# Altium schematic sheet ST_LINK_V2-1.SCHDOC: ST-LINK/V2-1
size A4; DocumentNumber: MB1167; Revision: B.1; SheetNumber: 15; SheetTotal: 17; Project: STM327x6G-EVAL
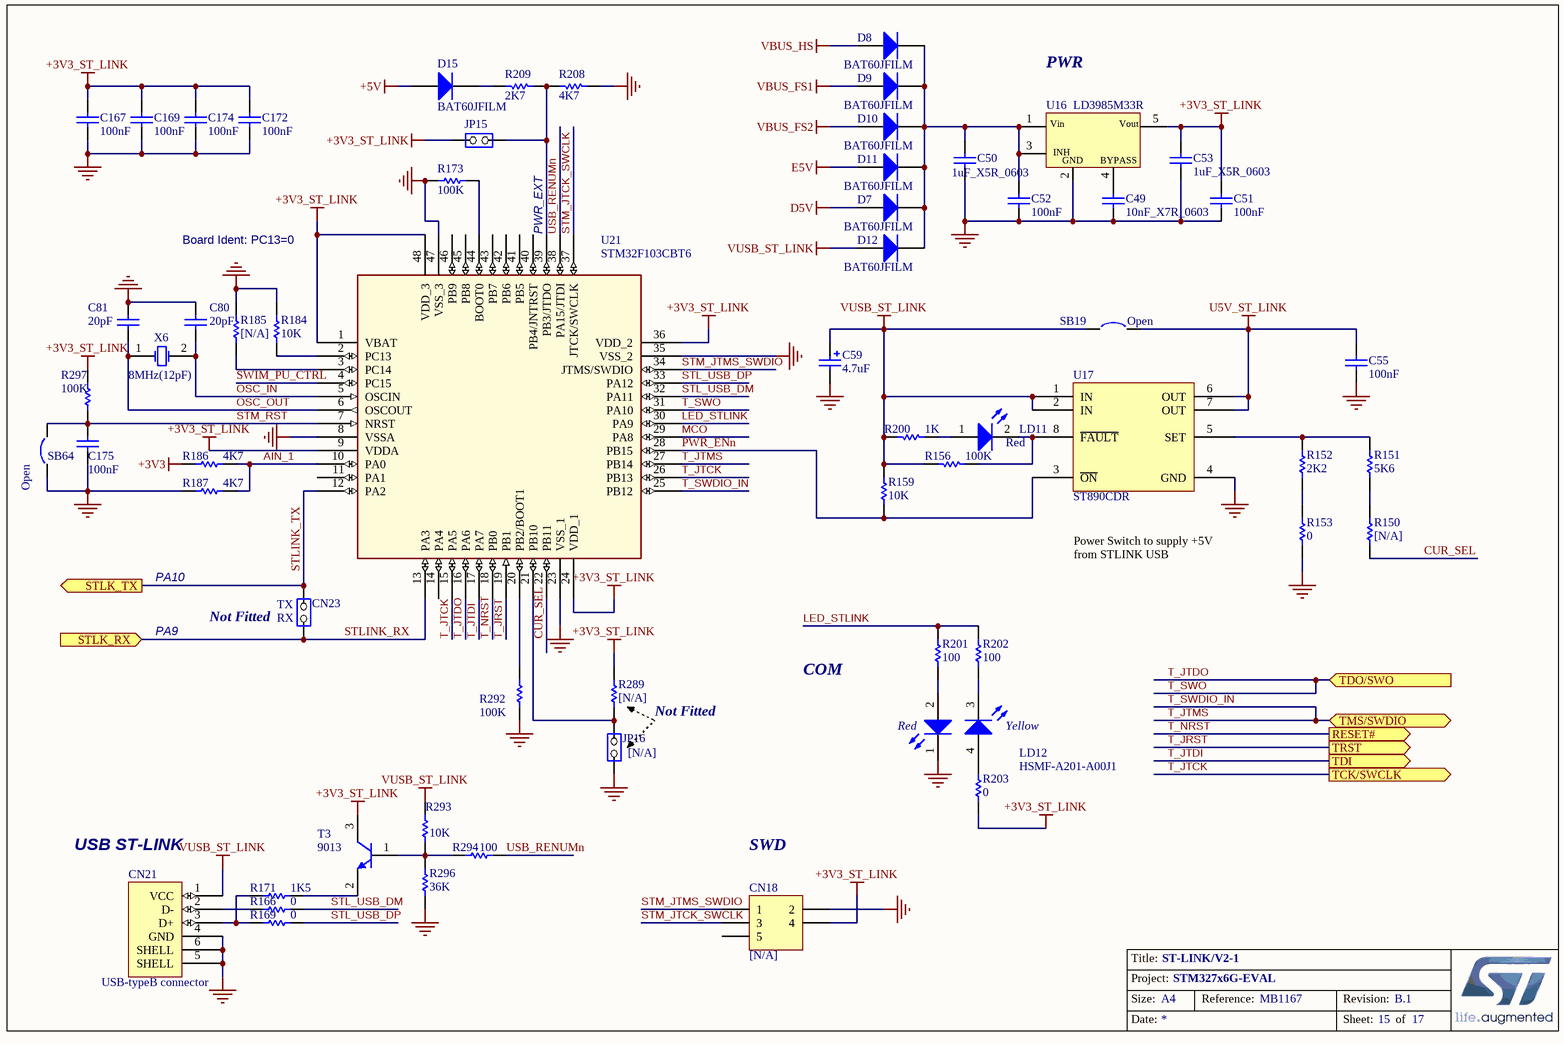
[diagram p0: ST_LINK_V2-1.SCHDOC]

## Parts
C49  10nF_X7R_0603  [0603C]
C50  1uF_X5R_0603  [0603C]
C51  100nF  [0603C]
C52  100nF  [0603C]
C53  1uF_X5R_0603  [0603C]
C55  100nF  [0603C]
C59  4.7uF  [TAN-A]
C80  20pF  [0603C]
C81  20pF  [0603C]
C167  100nF  [0603C]
C169  100nF  [0603C]
C172  100nF  [0603C]
C174  100nF  [0603C]
C175  100nF  [0603C]
CN18  [N/A]  [HDR_2X3-1_2R54-6]
CN21  USB-typeB connector  [USB-B]
CN23  (no value)  [SIP2]
D7  BAT60JFILM  [SOD-323]
D8  BAT60JFILM  [SOD-323]
D9  BAT60JFILM  [SOD-323]
D10  BAT60JFILM  [SOD-323]
D11  BAT60JFILM  [SOD-323]
D12  BAT60JFILM  [SOD-323]
D15  BAT60JFILM  [SOD-323]
JP15  (no value)  [SIP2]
JP16  [N/A]  [SIP2]
LD11  Red  [0603D]
LD12  HSMF-A201-A00J1  [LED2_3528]
R150  [N/A]  [0603R]
R151  5K6  [0402R]
R152  2K2  [0402R]
R153  0  [0603R]
R156  100K  [0603R]
R159  10K  [0402R]
R166  0  [0603R]
R169  0  [0603R]
R171  1K5  [0603R]
R173  100K  [0603R]
R184  10K  [0603R]
R185  [N/A]  [0603R]
R186  4K7  [0603R]
R187  4K7  [0603R]
R200  1K  [0603R]
R201  100  [0603R]
R202  100  [0603R]
R203  0  [0603R]
R208  4K7  [0603R]
R209  2K7  [0603R]
R289  [N/A]  [0603R]
R292  100K  [0603R]
R293  10K  [0603R]
R294  100  [0603R]
R296  36K  [0603R]
R297  100K  [0603R]
SB19  Open  [SB_0603]
SB64  Open  [SB_0603]
T3  9013  [SOT-23]
U16  LD3985M33R  [SOT23-5]
U17  ST890CDR  [SOIC8_1R27_4R9X6]
U21  STM32F103CBT6  [LQFP48_0R5_9X9]
X6  8MHz(12pF)  [XTAL_2SM_12R7X4R7]

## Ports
RESET# (out), STLK_RX (in), STLK_TX (out), TCK/SWCLK (out), TDI (out), TDO/SWO (in), TMS/SWDIO (bidir), TRST (out)

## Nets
+3V3: R186.1
+3V3_ST_LINK: C51.2 C53.1 C167.2 C169.2 C172.2 C174.2 CN18.4 JP15.1(COMMON) R203.2 R289.1 R297.2 T3.3(C) U16.5(Vout) U21.1(VBAT) U21.9(VDDA) U21.24(VDD_1) U21.36(VDD_2) U21.48(VDD_3)
+5V: D15.1(A)
D5V: D7.1(A)
E5V: D11.1(A)
GND: C49.1 C50.1 C51.1 C52.1 C53.2 C55.1 C59.2 C80.2 C81.2 C167.1 C169.1 C172.1 C174.1 C175.1 CN18.2 CN21.4(GND) CN21.5(SHELL) CN21.6(SHELL) JP16.1(COMMON) LD12.1(RED_cathode) R153.1 R173.1 R184.1 R185.1 R187.1 R208.2 R292.1 R296.1 SB64.1 U16.2(GND) U17.4(GND) U21.8(VSSA) U21.23(VSS_1) U21.35(VSS_2) U21.47(VSS_3)
U5V_ST_LINK: C55.2 SB19.2 U17.6(OUT) U17.7(OUT)
VBUS_FS1: D9.1(A)
VBUS_FS2: D10.1(A)
VBUS_HS: D8.1(A)
VUSB_ST_LINK: C59.1 CN21.1(VCC) D12.1(A) R156.1 R159.1 R200.1 R293.2 SB19.1 U17.1(IN) U17.2(IN)
AIN_1: R186.2 R187.2 U21.10(PA0)
CUR_SEL: R150.1 U21.22(PB11)
LED_STLINK: R201.1 R202.1 U21.30(PA9)
MCO: U21.29(PA8)
OSC_IN: C80.1 U21.5(OSCIN) X6.2(OSC2)
OSC_OUT: C81.1 U21.6(OSCOUT) X6.1(OSC1)
PWR_ENn: R159.2 U17.3(~{ON}) U21.28(PB15)
STL_USB_DM: R166.2 U21.32(PA11)
STL_USB_DP: R169.2 U21.33(PA12)
STLINK_RX: CN23.1(COMMON) U21.13(PA3) ; port STLK_RX
STLINK_TX: CN23.2(NO) U21.12(PA2) ; port STLK_TX
STM_JTCK_SWCLK: CN18.3 U21.37(JTCK/SWCLK)
STM_JTMS_SWDIO: CN18.1 U21.34(JTMS/SWDIO)
STM_RST: C175.2 R297.1 SB64.2 U21.7(NRST)
SWIM_PU_CTRL: U21.4(PC15)
T_JRST: U21.19(PB1) ; port TRST
T_JTCK: U21.15(PA5) U21.26(PB13) ; port TCK/SWCLK
T_JTDI: U21.17(PA7) ; port TDI
T_JTDO: U21.16(PA6) U21.31(PA10) ; port TDO/SWO  [also labelled T_SWO]
T_JTMS: U21.25(PB12) U21.27(PB14) ; port TMS/SWDIO  [also labelled T_SWDIO_IN]
T_NRST: U21.18(PB0) ; port RESET#
USB_RENUMn: R294.2 U21.38(PA15/JTDI)
NetC49_2: C49.2 U16.4(BYPASS)
NetC50_2: C50.2 C52.2 D7.2(K) D8.2(K) D9.2(K) D10.2(K) D11.2(K) D12.2(K) U16.1(Vin) U16.3(CE)
NetCN21_2: CN21.2(D-) R166.1
NetCN21_3: CN21.3(D+) R169.1 R171.1
NetD15_2: D15.2(K) R209.1
NetJP15_2: JP15.2(NO) R208.1 R209.2 U21.39(PB3/JTDO)
NetJP16_2: JP16.2(NO) R289.2 U21.21(PB10)
NetLD11_1: LD11.1(A) R200.2
NetLD11_2: LD11.2(K) R156.2 U17.8(~{FAULT})
NetLD12_2: LD12.2(Red_anode) R201.2
NetLD12_3: LD12.3(YellowGreen_cathode) R202.2
NetLD12_4: LD12.4(YellowGreen_anode) R203.1
NetR150_2: R150.2 R151.1
NetR151_2: R151.2 R152.2 U17.5(SET)
NetR152_1: R152.1 R153.2
NetR171_2: R171.2 T3.2(E)
NetR173_2: R173.2 U21.44(BOOT0)
NetR184_2: R184.2 U21.2(PC13)
NetR185_2: R185.2 U21.3(PC14)
NetR292_2: R292.2 U21.20(PB2/BOOT1)
NetR293_1: R293.1 R294.1 R296.2 T3.1(B)

Not connected (* = marked no-connect by the designer): CN18 5; U21 11(PA1) 14(PA4) 40(PB4/JNTRST) 41(PB5) 42(PB6) 43(PB7) 45(PB8) 46(PB9)

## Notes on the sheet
- PWR
- Board Ident: PC13=0
- (near U21) PWR_EXT
- PA10
- Power Switch to supply +5V from STLINK USB
- PA9
- (near CN23) Not Fitted
- (near CN23) TX
- (near CN23) RX
- Not Fitted
- COM
- (near CN21) USB ST-LINK
- SWD

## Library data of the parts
C49 = CAP SMD 0603  X7R 10000PF 50V 10%: 0603  X7R 10NF; Order code RS: 2040779; Rated voltage: 50V; Tolerance: 10%
C50 C53 = CAP SMD 0603  X5R 1µF 25V 10%: 0603  X5R 1µF; Rated voltage: 25V; Tolerance: 10%
C51 C52 C55 C167 C169 C172 C174 C175 = Capacitor_ST: Capacitor 0402 / 0603 / 0805
C59 = Cap Pol1: Polarized Capacitor (Radial); Value: 100pF; Ordered by: Subcon
C80 C81 = Capacitor_ST: Capacitor 0402 / 0603 / 0805; Value: 100nF
CN18 = Header 3X2: Header, 3-Pin, Dual row
CN23 = JP2: Fitted: NO
D7-D12 = BAT60JFILM: Manuf_1: STM; Provided: ST; ECCN_US/EU: EAR99/NEC
D15 = Diode: Default Diode; Code - JEDEC: DO-214-AB; Ordered by: STM; ECCN_US/EU: EAR99/NEC
JP15 = JP2: Ordered by: Subcon; Silkscreen: Pwr_ext
JP16 = JP2
LD11 = LED2: Typical RED, GREEN, YELLOW, AMBER GaAs LED
R150 R153 R201-R203 R208 R209 R289 R293 R296 = Res1: Resistor; Value: 1K
R151 R152 R166 R169 R171 R173 R292 R294 R297 = Resistor_ST: Resistor 0402 / 0603 / 0805; Description: Resistor 0402 or 0603 or 0805; Value: 10K
R156 = Res1: Resistor; Value: 1K; Ordered by: Subcon
R159 R184 = Resistor_ST: Resistor 0402 / 0603 / 0805; Description: Resistor 0402 or 0603 or 0805
R185-R187 = Resistor_ST: Resistor 0402 / 0603 / 0805; Description: Resistor 0402 or 0603 or 0805; Value: 10K; Fitted: NO
R200 = Res1: Resistor; Ordered by: Subcon
SB19 SB64 = Circuit Breaker
T3 = NPN: NPN Bipolar Transistor; Code - JEDEC: TO-226-AA
U16 = LD3985M33R: Ultra low drop-low noise BiCMOS voltage, regulators low ESR capacitors compatible; Manuf_1: STM; Provided: ST; Ref St: 9176161; ECCN_US/EU: EAR99/NEC
U21 = STM32F103CBT6: Medium-density performance line ARM-based 32-bit MCU with 64KB Flash; Manuf_Part_1: STM32F103C8T6; Manuf_1: STM; Ref St: 9175981; Provided: ST; ECCN_US/EU: 3A991A2/NEC
X6 = XTAL: Crystal Oscillator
